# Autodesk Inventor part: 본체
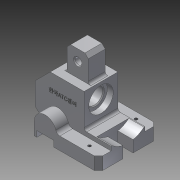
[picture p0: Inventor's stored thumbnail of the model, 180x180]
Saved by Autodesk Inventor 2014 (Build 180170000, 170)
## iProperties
Created: 2016-11
Part Number: 본체
Material: 알루미늄 6061
Document SubType Name: Modeling
Designer: USER
Density: 2.71 g/cm^3
Appearance: 알루미늄 - 평지
Mass: 460.528 g
Surface Area: 318.296 cm^2
Volume: 169.936 cm^3
Author: USER
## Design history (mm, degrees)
sketch "스케치1"
  geometry: L1 (0, 0)-(0, 15); L2 (0, 0)-(-63, 0); L3 (-76, 15)-(-76, 0); L4 (-63, 0)-(-76, 0); L5 (0, 15)-(-50, 15); A1 r 13 centre (-63, 15) between (-50, 15) and (-76, 15)
  constraints: 10 end point, 3 perpendicular, 2 point on circle, 1 centre point, 1 parallel, 1 tangent, 1 vertical, 1 vertical alignment
  dimensions: "d0" = 15 distance of L1.start L1.end; "d1" = 63 distance of L1.start L2.end; "d2" = 26 diameter of A1; "d3" = 15 distance from line of A1.centre L2
extrude "돌출1" new body sketch "스케치1" distance "d4" = 70; taper "d5" = 0 deg
sketch "스케치2"
  geometry: L1 (76, -15)-(76, 0) reference; L2 (76, 0)-(0, 0) reference; L3 (73, 0)-(53, 0); L4 (53, 0)-(53, -7); L5 (53, -7)-(73, -7); L6 (73, -7)-(73, 0)
  constraints: 8 end point, 2 parallel, 1 horizontal, 1 perpendicular, 1 point on line
  dimensions: "d6" = 3 distance between parallel lines of L1 L6; "d7" = 20 distance of L4.end L5.end; "d8" = 7 distance of L5.end L3.start
extrude "돌출2" cut sketch "스케치2" distance "d9" = 70; taper "d10" = 0 deg
node "작업 평면1"
sketch "스케치3"
  geometry: L1 (53, 0)-(53, -7) reference; L2 (53, -7)-(73, -7) reference; L3 (73, -7)-(73, 0) reference; L4 (76, 0)-(73, 0) reference; L5 (76, -15)-(76, 0) reference; L6 (0, -15)-(50, -15) reference; L7 (0, 0)-(0, -15) reference; L8 (53, 0)-(0, 0) reference; L9 (76, -12)-(90, -12); L10 (90, -12)-(90, -42); L11 (90, -42)-(72, -60); L12 (72, -60)-(32, -60); L13 (32, -60)-(32, -20); L14 (32, -20)-(0, -20); L15 (0, -20)-(0, -15); A1 r 13 centre (63, -15) between (50, -15) and (76, -15) reference; 1 further point
  constraints: 14 end point, 4 parallel, 2 perpendicular, 1 point on circle, 1 point on line
  dimensions: "d25" = 20 distance between parallel lines of L14 L8; "d26" = 90 distance between parallel lines of L15 L10; "d27" = 58 distance between parallel lines of L10 L13; "d28" = 45 deg angle of L12 L11; "d29" = 30 distance from line of L9 L10.end; "d30" = 48 distance between parallel lines of L9 L12; "d31" = 60 distance between parallel lines of L12 L8
extrude "돌출3" join sketch "스케치3" stored distance "d32" = 40; taper "d33" = 0 deg
sketch "스케치4"
  geometry: L1 (0, 0)-(0, 40) reference; L2 (-60, -15)-(-60, 55) reference; C1 r 14.5 at (-18, 20); 2 further points
  constraints: 2 midpoint, 1 centre point, 1 horizontal alignment
  dimensions: "d34" = 29 diameter of C1; "d90" = 42 distance from line of L2 C1.centre
extrude "돌출4" cut sketch "스케치4" distance "d35" = 7; taper "d36" = 0 deg
sketch "스케치5"
  geometry: C1 r 14.5 at (0, 0) reference; C2 r 10 at (0, 0); 1 further point
  constraints: 1 centre point, 1 coincident
  dimensions: "d37" = 20 diameter of C2
extrude "돌출5" cut sketch "스케치5" stored distance "d38" = 7; taper "d39" = 0 deg
node "작업 평면2"
sketch "스케치8"
  geometry: L1 (37, 90)-(62, 90); L2 (62, 90)-(62, 60); L3 (62, 60)-(37, 60); L4 (37, 60)-(37, 90); L5 (32, 20)-(32, 60) reference; 1 further point
  constraints: 8 end point, 2 parallel, 1 horizontal, 1 horizontal alignment, 1 perpendicular
  dimensions: "d47" = 25 distance of L1.start L1.end; "d48" = 5 distance between parallel lines of L4 L5; "d49" = 30 distance of L1.end L2.end
extrude "돌출8" join sketch "스케치8" stored distance "d50" = 20; taper "d51" = 0 deg
sketch "스케치9"
  geometry: L1 (37, -60)-(37, -90) reference; L2 (53, 0)-(0, 0) reference; L3 (32, -56.5)-(32, -27.5) reference; L4 (32, -42)-(26.5, -42); C1 r 4 at (49.5, -77)
  constraints: 2 end point, 1 centre point, 1 midpoint, 1 perpendicular
  dimensions: "d52" = 8 diameter of C1; "d53" = 12.5 distance from line of C1.centre L1; "d89" = 35 distance from line of C1.centre L4
extrude "돌출9" cut sketch "스케치9" stored distance "d55" = 20; taper "d56" = 0 deg
sketch "스케치10"
  geometry: L1 (0, -15)-(0, 0) reference; L2 (90, -25)-(90, -45) reference; L3 (90, -35)-(97.886, -35); 4 further points
  constraints: 2 end point, 1 midpoint, 1 perpendicular
  dimensions: "d57" = 27.5 distance from line of point (18, -7.5) L3; "d58" = 18 distance from line of point (18, -7.5) L1
hole "구멍1" sketch "스케치10" at (18, -7.5) diameter "d59" = 3.459; stored, may be unused: countersink angle "d63" = 90 deg, drill point angle "d65" = 118 deg; dims "d60" = 6, "d61" = 4, "d62" = 2, "d64" = 8
node "작업 평면3"
fillet "모깎기1" dims "d66" = 5
fillet "모깎기2" dims "d67" = 5
chamfer "모따기1" distance "d68" = 4; stored, may be unused: second distance "d69" = 2, angle "d70" = 45 deg
chamfer "모따기2" distance "d71" = 4; stored, may be unused: second distance "d72" = 2, angle "d73" = 45 deg
fillet "모깎기3" dims "d74" = 3
fillet "모깎기4" dims "d75" = 3
sketch "스케치11"
  geometry: L1 (32, -23)-(32, -60) reference; L2 (32, -60)-(72, -60) reference; 2 further points
  constraints: 1 other
  dimensions: "d76" = 18 distance from line of point (57, -42) L2; "d77" = 25 distance from line of point (57, -42) L1
extrude "돌출10" join sketch "스케치11" distance "d78" = 0.5; taper "d79" = 0 deg
chamfer "모따기3" distance "d80" = 5; stored, may be unused: second distance "d81" = 2, angle "d82" = 45 deg
chamfer "모따기4" distance "d83" = 1; stored, may be unused: second distance "d84" = 2, angle "d85" = 45 deg
chamfer "모따기5" distance "d86" = 1; stored, may be unused: second distance "d87" = 2, angle "d88" = 45 deg
sketch "스케치12"
  geometry: L1 (0, 0)-(0, 40) reference; C1 r 14.5 at (22, 20) reference; A1 r 29 centre (22, 20) between (0, 38.894) and (0, 1.106); 1 further point
  constraints: 2 point on circle, 2 point on line, 1 centre point, 1 coincident
  dimensions: "d91" = 58 diameter of A1
extrude "돌출11" cut sketch "스케치12" distance "d92" = 18; taper "d93" = 0 deg
sketch "스케치13"
  geometry: L1 (15.059, -14)-(-15, -14); L2 (-15, -14)-(-15, -26); L3 (-15, -26)-(15.059, -26); L4 (15.059, -26)-(15.059, -14); A1 r 29 centre (27, -20) between (5, -1.106) and (5, -38.894) reference; 4 further points
  constraints: 8 end point, 2 midpoint, 2 parallel, 1 horizontal, 1 horizontal alignment, 1 perpendicular, 1 point on circle, 1 vertical alignment
  dimensions: "d94" = 12 distance of L3.end L1.start; "d95" = 30.0587 distance of L2.end L3.end
extrude "돌출12" cut sketch "스케치13" distance "d96" = 18; taper "d97" = 0 deg
chamfer "모따기6" distance "d98" = 1; stored, may be unused: second distance "d99" = 2, angle "d100" = 45 deg
node "작업 평면4"
node "솔리드1"
mirror "대칭1"
node "투영된 루프1"
other parameters: "d15" = 48, "d17" = 5
